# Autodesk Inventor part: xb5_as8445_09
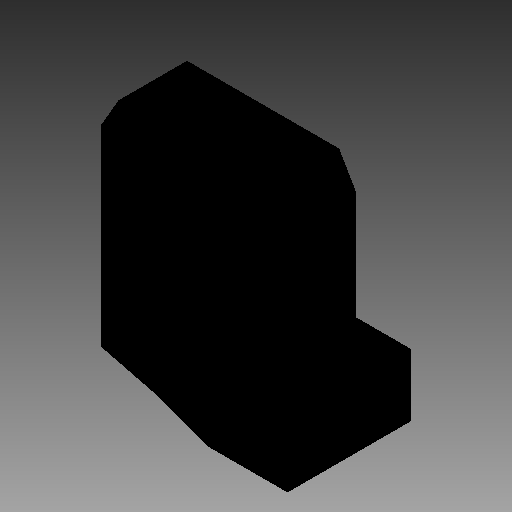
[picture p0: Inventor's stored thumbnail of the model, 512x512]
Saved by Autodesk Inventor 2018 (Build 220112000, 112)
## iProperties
Company: TraceParts S.A.
Created: 2018-04
Part Number: xb5_as8445_09
Checked By: TraceParts S.A.
Material: Generic
Catalog Web Link: www.traceparts.com
Document SubType Name: Modeling
Designer: TraceParts
Density: 1 g/cm^3
Appearance: Default
Author: TraceParts
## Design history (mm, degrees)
feature "xb5_as8445_09.ipt"
body "Solid1"
